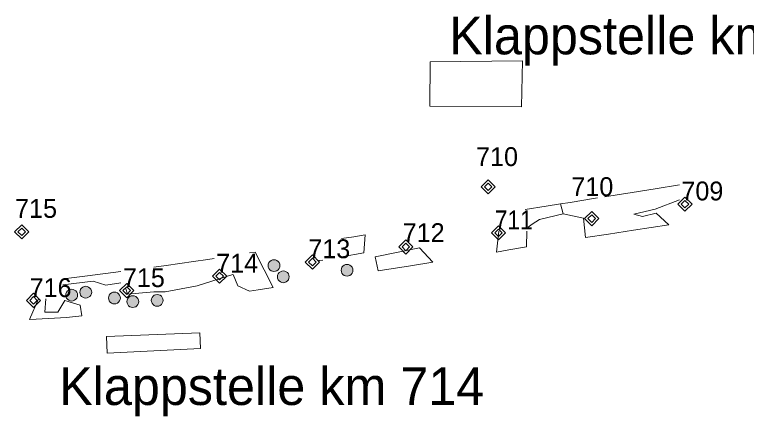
# Model space of a CAD drawing. Extents: x 3461750 to 3585707, y 5917729 to 5985917.
# Drawn here: x 3490496 to 3498273, y 5966343 to 5970607 of the extents above; entities that cross this region are included whole.
import ezdxf

# ---------------------------------------------------------------- set-up
doc = ezdxf.new("R2010")
doc.units = 0
doc.header["$LTSCALE"] = 80
doc.layers.add('11', color=7, linetype='Continuous')
for name, color, linetype, lineweight in [('12', 7, 'Continuous', 13), ('13', 7, 'Continuous', 13), ('14', 7, 'Continuous', 13), ('15', 7, 'Continuous', 13), ('2', 7, 'Continuous', 13), ('3', 7, 'Continuous', 13), ('6', 7, 'Continuous', 13)]:
    doc.layers.add(name, color=color, linetype=linetype, lineweight=lineweight)

msp = doc.modelspace()

# ---------------------------------------------------------------- hatches: boundary and pattern name
at = {"layer": '3'}
for points in [[(3493315.62, 5967943.22), (3493312.69, 5967959.85), (3493306.44, 5967974.94), (3493296.49, 5967987.9), (3493283.53, 5967997.84), (3493268.44, 5968004.09), (3493252.25, 5968006.23), (3493236.05, 5968004.09), (3493220.96, 5967997.84), (3493208, 5967987.9), (3493198.05, 5967974.94), (3493191.8, 5967959.85), (3493189.67, 5967943.65), (3493191.8, 5967927.46), (3493198.05, 5967912.36), (3493208, 5967899.4), (3493220.96, 5967889.46), (3493236.05, 5967883.21), (3493252.25, 5967881.08), (3493268.44, 5967883.21), (3493283.53, 5967889.46), (3493296.49, 5967899.4), (3493306.44, 5967912.36), (3493312.69, 5967927.46)], [(3494092.03, 5967893.61), (3494089.1, 5967910.24), (3494082.85, 5967925.33), (3494072.91, 5967938.29), (3494059.95, 5967948.23), (3494044.86, 5967954.49), (3494028.66, 5967956.62), (3494012.47, 5967954.49), (3493997.37, 5967948.23), (3493984.41, 5967938.29), (3493974.47, 5967925.33), (3493968.22, 5967910.24), (3493966.09, 5967894.04), (3493968.22, 5967877.85), (3493974.47, 5967862.76), (3493984.41, 5967849.8), (3493997.37, 5967839.85), (3494012.47, 5967833.6), (3494028.66, 5967831.47), (3494044.86, 5967833.6), (3494059.95, 5967839.85), (3494072.91, 5967849.8), (3494082.85, 5967862.76), (3494089.1, 5967877.85)], [(3493414.45, 5967824.18), (3493411.52, 5967840.8), (3493405.27, 5967855.9), (3493395.32, 5967868.86), (3493382.36, 5967878.8), (3493367.27, 5967885.05), (3493351.07, 5967887.18), (3493334.88, 5967885.05), (3493319.79, 5967878.8), (3493306.83, 5967868.86), (3493296.88, 5967855.9), (3493290.63, 5967840.8), (3493288.5, 5967824.61), (3493290.63, 5967808.41), (3493296.88, 5967793.32), (3493306.83, 5967780.36), (3493319.79, 5967770.42), (3493334.88, 5967764.17), (3493351.07, 5967762.03), (3493367.27, 5967764.17), (3493382.36, 5967770.42), (3493395.32, 5967780.36), (3493405.27, 5967793.32), (3493411.52, 5967808.41)], [(3491164.94, 5967629.55), (3491162.01, 5967646.18), (3491155.75, 5967661.27), (3491145.81, 5967674.23), (3491132.85, 5967684.17), (3491117.76, 5967690.42), (3491101.56, 5967692.56), (3491085.37, 5967690.42), (3491070.28, 5967684.17), (3491057.32, 5967674.23), (3491047.37, 5967661.27), (3491041.12, 5967646.18), (3491038.99, 5967629.98), (3491041.12, 5967613.78), (3491047.37, 5967598.69), (3491057.32, 5967585.73), (3491070.28, 5967575.79), (3491085.37, 5967569.54), (3491101.56, 5967567.4), (3491117.76, 5967569.54), (3491132.85, 5967575.79), (3491145.81, 5967585.73), (3491155.75, 5967598.69), (3491162.01, 5967613.78)], [(3491314.4, 5967660.22), (3491311.47, 5967676.84), (3491305.22, 5967691.93), (3491295.27, 5967704.89), (3491282.31, 5967714.84), (3491267.22, 5967721.09), (3491251.02, 5967723.22), (3491234.83, 5967721.09), (3491219.74, 5967714.84), (3491206.78, 5967704.89), (3491196.83, 5967691.93), (3491190.58, 5967676.84), (3491188.45, 5967660.64), (3491190.58, 5967644.45), (3491196.83, 5967629.36), (3491206.78, 5967616.4), (3491219.74, 5967606.45), (3491234.83, 5967600.2), (3491251.02, 5967598.07), (3491267.22, 5967600.2), (3491282.31, 5967606.45), (3491295.27, 5967616.4), (3491305.22, 5967629.36), (3491311.47, 5967644.45)], [(3491619.57, 5967599.08), (3491616.64, 5967615.71), (3491610.39, 5967630.8), (3491600.45, 5967643.76), (3491587.49, 5967653.7), (3491572.4, 5967659.95), (3491556.2, 5967662.09), (3491540.01, 5967659.95), (3491524.91, 5967653.7), (3491511.95, 5967643.76), (3491502.01, 5967630.8), (3491495.76, 5967615.71), (3491493.63, 5967599.51), (3491495.76, 5967583.32), (3491502.01, 5967568.22), (3491511.95, 5967555.26), (3491524.91, 5967545.32), (3491540.01, 5967539.07), (3491556.2, 5967536.94), (3491572.4, 5967539.07), (3491587.49, 5967545.32), (3491600.45, 5967555.26), (3491610.39, 5967568.22), (3491616.64, 5967583.32)], [(3491814.98, 5967560.9), (3491812.05, 5967577.52), (3491805.8, 5967592.62), (3491795.86, 5967605.58), (3491782.9, 5967615.52), (3491767.81, 5967621.77), (3491751.61, 5967623.9), (3491735.42, 5967621.77), (3491720.32, 5967615.52), (3491707.36, 5967605.58), (3491697.42, 5967592.62), (3491691.17, 5967577.52), (3491689.04, 5967561.33), (3491691.17, 5967545.13), (3491697.42, 5967530.04), (3491707.36, 5967517.08), (3491720.32, 5967507.14), (3491735.42, 5967500.89), (3491751.61, 5967498.75), (3491767.81, 5967500.89), (3491782.9, 5967507.14), (3491795.86, 5967517.08), (3491805.8, 5967530.04), (3491812.05, 5967545.13)], [(3492074.07, 5967573.59), (3492071.14, 5967590.22), (3492064.88, 5967605.31), (3492054.94, 5967618.27), (3492041.98, 5967628.21), (3492026.89, 5967634.47), (3492010.69, 5967636.6), (3491994.5, 5967634.47), (3491979.41, 5967628.21), (3491966.45, 5967618.27), (3491956.5, 5967605.31), (3491950.25, 5967590.22), (3491948.12, 5967574.02), (3491950.25, 5967557.83), (3491956.5, 5967542.74), (3491966.45, 5967529.78), (3491979.41, 5967519.83), (3491994.5, 5967513.58), (3492010.69, 5967511.45), (3492026.89, 5967513.58), (3492041.98, 5967519.83), (3492054.94, 5967529.78), (3492064.88, 5967542.74), (3492071.14, 5967557.83)]]:
    msp.add_hatch(color=256, dxfattribs=at).paths.add_polyline_path(points)

# ---------------------------------------------------------------- linework, layer by layer
at = {"layer": '12'}
for points in [[(3490570.64, 5968377.06), (3490495.55, 5968301.97), (3490570.64, 5968226.88), (3490645.73, 5968301.97)], [(3490570.64, 5968341.66), (3490530.95, 5968301.97), (3490570.64, 5968262.27), (3490610.33, 5968301.97)]]:
    msp.add_lwpolyline(points, close=True, dxfattribs=at)
at = {"layer": '13'}
for points in [[(3495529.23, 5968854.99), (3495454.14, 5968779.9), (3495529.23, 5968704.8), (3495604.32, 5968779.9)], [(3495529.23, 5968819.59), (3495489.54, 5968779.9), (3495529.23, 5968740.2), (3495568.92, 5968779.9)]]:
    msp.add_lwpolyline(points, close=True, dxfattribs=at)
at = {"layer": '14'}
for points in [[(3496629.48, 5968516.61), (3496554.39, 5968441.52), (3496629.48, 5968366.43), (3496704.57, 5968441.52)], [(3496629.48, 5968481.21), (3496589.78, 5968441.52), (3496629.48, 5968401.82), (3496669.17, 5968441.52)]]:
    msp.add_lwpolyline(points, close=True, dxfattribs=at)
at = {"layer": '15'}
for points in [[(3497620.54, 5968671.39), (3497545.45, 5968596.3), (3497620.54, 5968521.21), (3497695.63, 5968596.3)], [(3497620.54, 5968635.99), (3497580.85, 5968596.3), (3497620.54, 5968556.61), (3497660.23, 5968596.3)], [(3495638.75, 5968366.51), (3495563.66, 5968291.42), (3495638.75, 5968216.33), (3495713.84, 5968291.42)], [(3495638.75, 5968331.11), (3495599.06, 5968291.42), (3495638.75, 5968251.73), (3495678.45, 5968291.42)], [(3494654.77, 5968216.51), (3494579.68, 5968141.42), (3494654.77, 5968066.33), (3494729.86, 5968141.42)], [(3494654.77, 5968181.11), (3494615.08, 5968141.42), (3494654.77, 5968101.73), (3494694.46, 5968141.42)], [(3493660.09, 5968056.06), (3493585, 5967980.97), (3493660.09, 5967905.88), (3493735.18, 5967980.97)], [(3493660.09, 5968020.66), (3493620.4, 5967980.97), (3493660.09, 5967941.28), (3493699.78, 5967980.97)], [(3492674.3, 5967906.06), (3492599.21, 5967830.97), (3492674.3, 5967755.88), (3492749.39, 5967830.97)], [(3492674.3, 5967870.66), (3492634.61, 5967830.97), (3492674.3, 5967791.28), (3492713.99, 5967830.97)], [(3491686.7, 5967752.35), (3491611.61, 5967677.26), (3491686.7, 5967602.17), (3491761.79, 5967677.26)], [(3491686.7, 5967716.95), (3491647.01, 5967677.26), (3491686.7, 5967637.57), (3491726.4, 5967677.26)], [(3490696.03, 5967649.32), (3490620.94, 5967574.23), (3490696.03, 5967499.14), (3490771.12, 5967574.23)], [(3490696.03, 5967613.92), (3490656.34, 5967574.23), (3490696.03, 5967534.54), (3490735.72, 5967574.23)]]:
    msp.add_lwpolyline(points, close=True, dxfattribs=at)
at = {"layer": '2'}
for p, q in [((3496298.19, 5968597.95), (3496326.12, 5968491.5)), ((3495941.6, 5968308.6), (3495937.89, 5968142.77)), ((3495937.89, 5968142.77), (3495747.46, 5968112.11)), ((3493050.88, 5968087.01), (3492991.1, 5968077.93)), ((3493242.63, 5967711.33), (3493050.88, 5968087.01)), ((3491626.1, 5967879.29), (3491269.92, 5967835.25)), ((3491331.54, 5967777.05), (3491008.3, 5967737.69)), ((3490749.69, 5967588.7), (3490654.59, 5967370.51))]:
    msp.add_line(p, q, dxfattribs=at)
for points in [[(3497562.4, 5968799.33), (3497305.32, 5968757.81), (3497058.11, 5968718.75), (3496766.4, 5968673.15)], [(3496691.9, 5968661.5), (3496671.44, 5968658.3), (3496401.95, 5968614.26), (3496298.19, 5968597.95)], [(3497562.4, 5968643.13), (3497303.52, 5968543.95), (3497078.22, 5968488.09), (3497169.92, 5968464.94), (3497313.62, 5968501.56), (3497447.71, 5968376.95)], [(3496298.19, 5968597.95), (3496143.85, 5968573.83), (3495922.2, 5968538.6)], [(3496326.12, 5968491.5), (3496074.46, 5968431.25), (3495998.14, 5968383.01), (3495953.3, 5968349.5)], [(3496326.12, 5968491.5), (3496541.02, 5968448.54), (3496562.99, 5968240.33)], [(3497447.71, 5968376.95), (3497074.46, 5968319.73), (3496808.3, 5968278.71), (3496562.99, 5968240.33)], [(3495747.46, 5968112.11), (3495616.6, 5968085.55), (3495643.58, 5968308.6)], [(3494222.61, 5968269.34), (3494100.68, 5968249.71), (3493970.6, 5968229.5)], [(3494222.61, 5968269.34), (3494206.79, 5968080.08), (3493970.6, 5968037.66)], [(3494941.26, 5967978.42), (3494799.17, 5968132.81), (3494329.44, 5968037.11), (3494360.69, 5967886.04)], [(3492617.5, 5968019.6), (3492549.22, 5968008.59), (3492397.07, 5967985.35), (3492105.08, 5967942.97), (3491975.64, 5967924.9)], [(3493770.92, 5968001.8), (3493732.08, 5967994.82), (3493731.64, 5968001.8)], [(3494941.26, 5967978.42), (3494704.79, 5967941.7), (3494360.69, 5967886.04)], [(3491269.92, 5967835.25), (3491013.43, 5967803.52), (3491008.3, 5967803.07)], [(3492814.42, 5967848.4), (3492435.25, 5967726.86), (3492095.56, 5967665.92), (3491974.07, 5967665.43), (3491693.95, 5967640.43), (3491677.77, 5967694.9)], [(3492993.16, 5967672.85), (3492866.89, 5967727.05), (3492819.35, 5967848.4)], [(3491626.1, 5967759.1), (3491464.11, 5967735.94), (3491331.54, 5967777.05)], [(3493242.63, 5967711.33), (3493083.74, 5967686.62), (3492993.16, 5967672.85)], [(3491211.28, 5967409.77), (3491190.53, 5967523.63), (3491030.13, 5967571.58), (3490956.01, 5967448.93), (3490815.43, 5967447.36), (3490827.39, 5967588.7)], [(3491211.28, 5967409.77), (3491046.19, 5967392.48), (3490723.44, 5967374.22), (3490654.59, 5967370.51)]]:
    msp.add_lwpolyline(points, dxfattribs=at)
at = {"layer": '3'}
for points in [[(3493315.62, 5967943.22), (3493312.69, 5967959.85), (3493306.44, 5967974.94), (3493296.49, 5967987.9), (3493283.53, 5967997.84), (3493268.44, 5968004.09), (3493252.25, 5968006.23), (3493236.05, 5968004.09), (3493220.96, 5967997.84), (3493208, 5967987.9), (3493198.05, 5967974.94), (3493191.8, 5967959.85), (3493189.67, 5967943.65), (3493191.8, 5967927.46), (3493198.05, 5967912.36), (3493208, 5967899.4), (3493220.96, 5967889.46), (3493236.05, 5967883.21), (3493252.25, 5967881.08), (3493268.44, 5967883.21), (3493283.53, 5967889.46), (3493296.49, 5967899.4), (3493306.44, 5967912.36), (3493312.69, 5967927.46)], [(3494092.03, 5967893.61), (3494089.1, 5967910.24), (3494082.85, 5967925.33), (3494072.91, 5967938.29), (3494059.95, 5967948.23), (3494044.86, 5967954.49), (3494028.66, 5967956.62), (3494012.47, 5967954.49), (3493997.37, 5967948.23), (3493984.41, 5967938.29), (3493974.47, 5967925.33), (3493968.22, 5967910.24), (3493966.09, 5967894.04), (3493968.22, 5967877.85), (3493974.47, 5967862.76), (3493984.41, 5967849.8), (3493997.37, 5967839.85), (3494012.47, 5967833.6), (3494028.66, 5967831.47), (3494044.86, 5967833.6), (3494059.95, 5967839.85), (3494072.91, 5967849.8), (3494082.85, 5967862.76), (3494089.1, 5967877.85)], [(3493414.45, 5967824.18), (3493411.52, 5967840.8), (3493405.27, 5967855.9), (3493395.32, 5967868.86), (3493382.36, 5967878.8), (3493367.27, 5967885.05), (3493351.07, 5967887.18), (3493334.88, 5967885.05), (3493319.79, 5967878.8), (3493306.83, 5967868.86), (3493296.88, 5967855.9), (3493290.63, 5967840.8), (3493288.5, 5967824.61), (3493290.63, 5967808.41), (3493296.88, 5967793.32), (3493306.83, 5967780.36), (3493319.79, 5967770.42), (3493334.88, 5967764.17), (3493351.07, 5967762.03), (3493367.27, 5967764.17), (3493382.36, 5967770.42), (3493395.32, 5967780.36), (3493405.27, 5967793.32), (3493411.52, 5967808.41)], [(3491164.94, 5967629.55), (3491162.01, 5967646.18), (3491155.75, 5967661.27), (3491145.81, 5967674.23), (3491132.85, 5967684.17), (3491117.76, 5967690.42), (3491101.56, 5967692.56), (3491085.37, 5967690.42), (3491070.28, 5967684.17), (3491057.32, 5967674.23), (3491047.37, 5967661.27), (3491041.12, 5967646.18), (3491038.99, 5967629.98), (3491041.12, 5967613.78), (3491047.37, 5967598.69), (3491057.32, 5967585.73), (3491070.28, 5967575.79), (3491085.37, 5967569.54), (3491101.56, 5967567.4), (3491117.76, 5967569.54), (3491132.85, 5967575.79), (3491145.81, 5967585.73), (3491155.75, 5967598.69), (3491162.01, 5967613.78)], [(3491314.4, 5967660.22), (3491311.47, 5967676.84), (3491305.22, 5967691.93), (3491295.27, 5967704.89), (3491282.31, 5967714.84), (3491267.22, 5967721.09), (3491251.02, 5967723.22), (3491234.83, 5967721.09), (3491219.74, 5967714.84), (3491206.78, 5967704.89), (3491196.83, 5967691.93), (3491190.58, 5967676.84), (3491188.45, 5967660.64), (3491190.58, 5967644.45), (3491196.83, 5967629.36), (3491206.78, 5967616.4), (3491219.74, 5967606.45), (3491234.83, 5967600.2), (3491251.02, 5967598.07), (3491267.22, 5967600.2), (3491282.31, 5967606.45), (3491295.27, 5967616.4), (3491305.22, 5967629.36), (3491311.47, 5967644.45)], [(3491619.57, 5967599.08), (3491616.64, 5967615.71), (3491610.39, 5967630.8), (3491600.45, 5967643.76), (3491587.49, 5967653.7), (3491572.4, 5967659.95), (3491556.2, 5967662.09), (3491540.01, 5967659.95), (3491524.91, 5967653.7), (3491511.95, 5967643.76), (3491502.01, 5967630.8), (3491495.76, 5967615.71), (3491493.63, 5967599.51), (3491495.76, 5967583.32), (3491502.01, 5967568.22), (3491511.95, 5967555.26), (3491524.91, 5967545.32), (3491540.01, 5967539.07), (3491556.2, 5967536.94), (3491572.4, 5967539.07), (3491587.49, 5967545.32), (3491600.45, 5967555.26), (3491610.39, 5967568.22), (3491616.64, 5967583.32)], [(3491814.98, 5967560.9), (3491812.05, 5967577.52), (3491805.8, 5967592.62), (3491795.86, 5967605.58), (3491782.9, 5967615.52), (3491767.81, 5967621.77), (3491751.61, 5967623.9), (3491735.42, 5967621.77), (3491720.32, 5967615.52), (3491707.36, 5967605.58), (3491697.42, 5967592.62), (3491691.17, 5967577.52), (3491689.04, 5967561.33), (3491691.17, 5967545.13), (3491697.42, 5967530.04), (3491707.36, 5967517.08), (3491720.32, 5967507.14), (3491735.42, 5967500.89), (3491751.61, 5967498.75), (3491767.81, 5967500.89), (3491782.9, 5967507.14), (3491795.86, 5967517.08), (3491805.8, 5967530.04), (3491812.05, 5967545.13)], [(3492074.07, 5967573.59), (3492071.14, 5967590.22), (3492064.88, 5967605.31), (3492054.94, 5967618.27), (3492041.98, 5967628.21), (3492026.89, 5967634.47), (3492010.69, 5967636.6), (3491994.5, 5967634.47), (3491979.41, 5967628.21), (3491966.45, 5967618.27), (3491956.5, 5967605.31), (3491950.25, 5967590.22), (3491948.12, 5967574.02), (3491950.25, 5967557.83), (3491956.5, 5967542.74), (3491966.45, 5967529.78), (3491979.41, 5967519.83), (3491994.5, 5967513.58), (3492010.69, 5967511.45), (3492026.89, 5967513.58), (3492041.98, 5967519.83), (3492054.94, 5967529.78), (3492064.88, 5967542.74), (3492071.14, 5967557.83)]]:
    msp.add_lwpolyline(points, close=True, dxfattribs=at)
at = {"layer": '6'}
for points in [[(3494911.04, 5970108.2), (3494908.4, 5969635.55), (3495881.59, 5969628.71), (3495895.21, 5970116.8)], [(3491471, 5967192.29), (3491478.76, 5967014.36), (3492470.75, 5967064.65), (3492465.38, 5967229.39)]]:
    msp.add_lwpolyline(points, close=True, dxfattribs=at)

# ---------------------------------------------------------------- texts
at = {"layer": '11'}
for s, p in [('Klappstelle km 711 ', (3495114.5, 5970186)), ('Klappstelle km 714 ', (3490968.4, 5966463.6))]:
    msp.add_text(s, height=400, dxfattribs=at).set_placement(p)
at = {"layer": '12'}
msp.add_text('715', height=200, dxfattribs=at).set_placement((3490500, 5968450))
at = {"layer": '13'}
msp.add_text('710', height=200, dxfattribs=at).set_placement((3495400, 5969000))
at = {"layer": '14'}
msp.add_text('710', height=200, dxfattribs=at).set_placement((3496412.8, 5968681.5))
at = {"layer": '15'}
for s, p in [('709', (3497582.4, 5968635.4)), ('712', (3494620.1, 5968192.9)), ('713', (3493617, 5968021.8)), ('714', (3492637.5, 5967868.4)), ('715', (3491646.1, 5967714.9)), ('716', (3490654.7, 5967608.7))]:
    msp.add_text(s, height=200, dxfattribs=at).set_placement(p)
at = {"layer": '15', "width": 0.9}
msp.add_text('711', height=200, dxfattribs=at).set_placement((3495599.7, 5968328.6))

doc.saveas('drawing.dxf')
